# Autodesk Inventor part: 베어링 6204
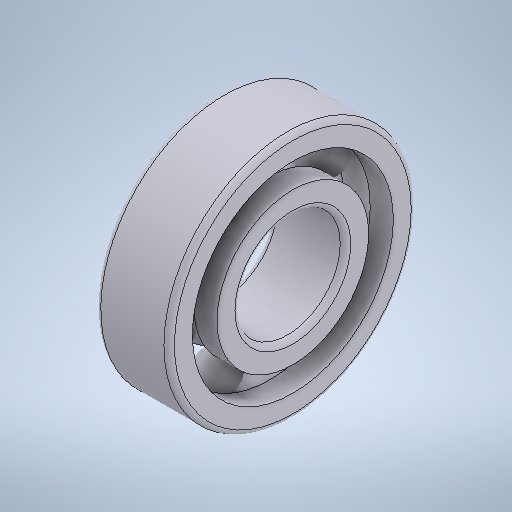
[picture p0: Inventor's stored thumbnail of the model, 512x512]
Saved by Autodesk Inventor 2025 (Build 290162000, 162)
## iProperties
Created: 2024-08
Part Number: 베어링 6204
Material: 강철, 연강
Description: 깊은 그루브 볼 베어링
Document SubType Name: Modeling
Designer: onair
Density: 7.86 g/cm^3
Appearance: 기본값
Author: jhkim
Sending System: Autodesk Inventor 2025
Preprocessor: ST-DEVELOPER v20
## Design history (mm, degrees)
feature "Solid1"
feature "Solid1:1"
feature "Solid1:2"
feature "Solid1:3"
feature "Solid1:4"
feature "Solid1:5"
feature "Solid1:6"
feature "Solid1:7"
feature "Solid1:8"
node "솔리드1"
node "솔리드2"
node "솔리드3"
node "솔리드4"
node "솔리드5"
node "솔리드6"
node "솔리드7"
node "솔리드8"
node "솔리드9"
